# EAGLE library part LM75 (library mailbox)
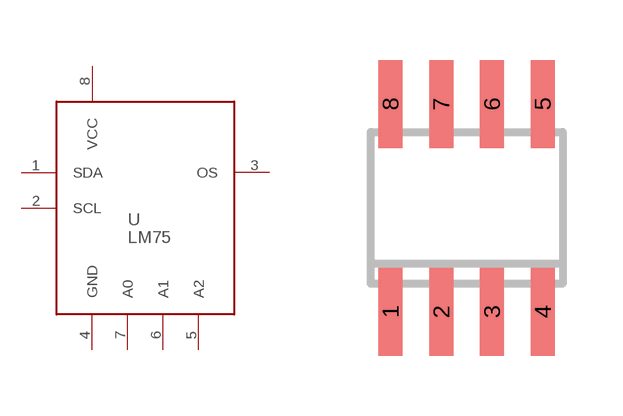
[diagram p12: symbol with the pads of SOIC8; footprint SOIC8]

Designator prefix -

## LM75  [SOIC8]
1  SDA
2  SCL
3  OS
4  GND
5  A2
6  A1
7  A0
8  VCC

## Footprint SOIC8 (pad centres in mm)
Small Outline IC
smd 0.6 x 2.2: 1 -1.905,-2.6; 2 -0.635,-2.6; 3 0.635,-2.6; 4 1.905,-2.6; 5 1.905,2.6; 6 0.635,2.6; 7 -0.635,2.6; 8 -1.905,2.6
